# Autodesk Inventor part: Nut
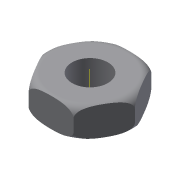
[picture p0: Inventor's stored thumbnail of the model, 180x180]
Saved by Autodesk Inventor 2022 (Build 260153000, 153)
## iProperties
Created: 2009-04
Part Number: Nut
Document SubType Name: Modeling
Designer: Sham
Density: 1 g/cm^3
Material: Generic
Appearance: Default
Mass: 4.65064 g
Surface Area: 21.3319 cm^2
Volume: 4.65064 cm^3
Author: Sham
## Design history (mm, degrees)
sketch "Sketch1"
  geometry: L1 (7.5, 12.99)-(15, 0); L2 (15, 0)-(7.5, -12.99); L3 (7.5, -12.99)-(-7.5, -12.99); L4 (-7.5, -12.99)-(-15, 0); L5 (-15, 0)-(-7.5, 12.99); L6 (-7.5, 12.99)-(7.5, 12.99); C1 r 6 at (0, 0); 1 further point
  constraints: 12 end point, 1 centre point, 1 coincident, 13 other
  dimensions: "d0" = 30 distance of L1.end L4.end; "d1" = 12 diameter of C1
extrude "Extrusion1" new body sketch "Sketch1" distance "d2" = 12; taper "d3" = 0 deg
sketch "Sketch2"
  geometry: L1 (-12, 0)-(-12, -0.022); L2 (-15, 7)-(-15, 3); L3 (0, -2.87)-(0, 12.87) reference; A1 r 3 centre (-12, 7) between (-12, 10) and (-15, 7); A2 r 3 centre (-12, 3) between (-15, 3) and (-12, 0)
  constraints: 4 end point, 4 point on circle, 2 centre point, 1 tangent
revolve "Revolution1" sketch "Sketch2" stored, may be unused: angle "d7" = 90 deg
body "Solid1"
other parameters: "d6" = 90 deg
